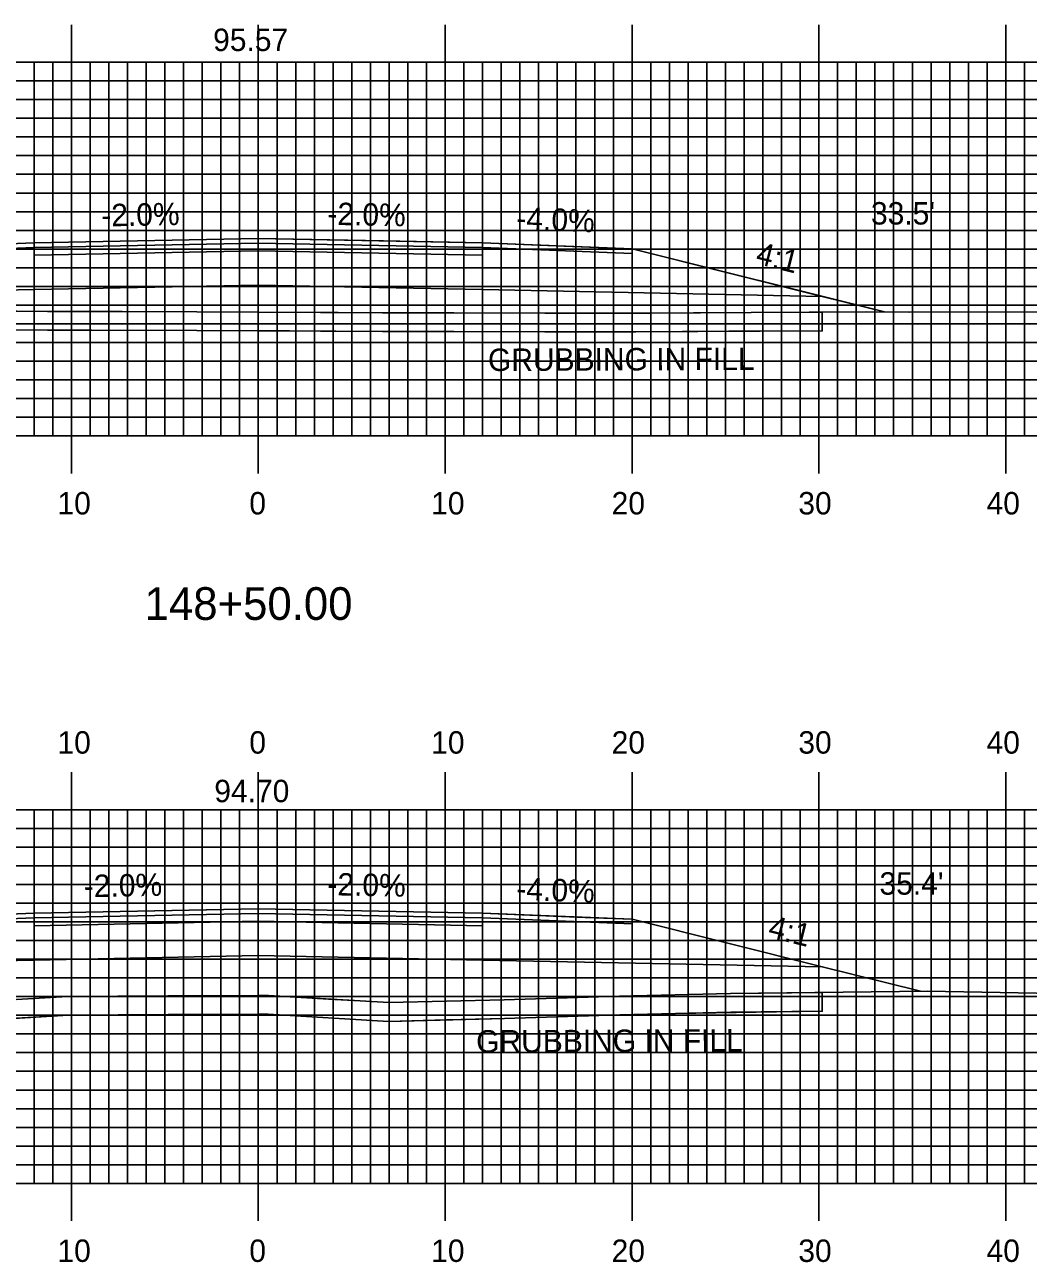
# Model space of a CAD drawing. Extents: x 1777925 to 1778268, y 442591 to 442811.
# Drawn here: x 1778078.3 to 1778132, y 442689.4 to 442755.7 of the extents above; entities that cross this region are included whole.
import ezdxf

# ---------------------------------------------------------------- set-up
doc = ezdxf.new("R2010")
doc.units = 0
for name, color, linetype in [('ANNOTATION', 7, 'Continuous'), ('D_Roadway_Centerline', 7, 'Continuous'), ('D_Roadway_Centerline_Text', 7, 'Continuous'), ('D_Roadway_Edge_Shoulder', 7, 'Continuous'), ('D_Roadway_Edge_TW', 7, 'Continuous'), ('D_Roadway_Pavement', 7, 'Continuous'), ('D_Roadway_SlopeLines', 7, 'Continuous'), ('D_Roadway_SubGrade', 7, 'Continuous'), ('D_Text_Standard', 7, 'Continuous'), ('GRUBBING IN FILL', 7, 'Continuous'), ('H_V ANNOTATION', 7, 'Continuous'), ('MAJOR', 7, 'Continuous'), ('MINOR', 7, 'Continuous'), ('S_Roadway_Centerline', 7, 'Continuous')]:
    doc.layers.add(name, color=color, linetype=linetype)

msp = doc.modelspace()

# ---------------------------------------------------------------- linework, layer by layer
at = {"layer": 'D_Roadway_Centerline'}
for points in [[(1778058.344, 442740.566), (1778060.616, 442741.134), (1778070.79, 442743.677), (1778078.79, 442743.997), (1778090.789, 442744.237), (1778090.79, 442744.237), (1778097.486, 442744.103), (1778102.79, 442743.997), (1778107.608, 442743.804), (1778110.79, 442743.677), (1778120.964, 442741.134), (1778124.306, 442740.299)], [(1778125.608, 442740.297), (1778125.616, 442740.297)], [(1778052.326, 442703.186), (1778053.506, 442703.481), (1778058.79, 442704.802), (1778059.096, 442704.879), (1778060.616, 442705.259), (1778065.395, 442706.454), (1778070.79, 442707.802), (1778078.79, 442708.122), (1778088.92, 442708.325), (1778090.79, 442708.362), (1778102.79, 442708.122), (1778108.283, 442707.902), (1778110.79, 442707.802), (1778120.964, 442705.259), (1778126.218, 442703.946)]]:
    msp.add_lwpolyline(points, dxfattribs=at)
at = {"layer": 'D_Roadway_Edge_Shoulder'}
for points in [[(1778078.79, 442743.997), (1778070.79, 442743.677), (1778070.79, 442743.427), (1778078.79, 442743.747)], [(1778102.79, 442743.997), (1778110.79, 442743.677), (1778110.79, 442743.427), (1778102.79, 442743.747)], [(1778078.79, 442708.122), (1778070.79, 442707.802), (1778070.79, 442707.552), (1778078.79, 442707.872)], [(1778102.79, 442708.122), (1778110.79, 442707.802), (1778110.79, 442707.552), (1778102.79, 442707.872)]]:
    msp.add_lwpolyline(points, close=True, dxfattribs=at)
at = {"layer": 'D_Roadway_Edge_TW'}
for points in [[(1778078.79, 442743.747), (1778078.79, 442743.997), (1778090.79, 442744.237), (1778102.79, 442743.997), (1778102.79, 442743.747), (1778090.79, 442743.987)], [(1778078.79, 442707.872), (1778078.79, 442708.122), (1778090.79, 442708.362), (1778102.79, 442708.122), (1778102.79, 442707.872), (1778090.79, 442708.112)]]:
    msp.add_lwpolyline(points, close=True, dxfattribs=at)
at = {"layer": 'D_Roadway_Pavement'}
for points in [[(1778078.79, 442743.331), (1778078.79, 442743.747), (1778090.79, 442743.987), (1778102.79, 442743.747), (1778102.79, 442743.331), (1778090.79, 442743.571)], [(1778078.79, 442707.456), (1778078.79, 442707.872), (1778090.79, 442708.112), (1778102.79, 442707.872), (1778102.79, 442707.456), (1778090.79, 442707.696)]]:
    msp.add_lwpolyline(points, close=True, dxfattribs=at)
at = {"layer": 'D_Roadway_SlopeLines'}
for points in [[(1778110.79, 442743.677), (1778124.305, 442740.299)], [(1778110.79, 442707.802), (1778120.964, 442705.259), (1778126.218, 442703.946)]]:
    msp.add_lwpolyline(points, dxfattribs=at)
at = {"layer": 'D_Roadway_SubGrade'}
for points in [[(1778078.79, 442741.497), (1778060.616, 442741.134), (1778070.79, 442743.677), (1778070.79, 442743.427), (1778078.79, 442743.747), (1778090.79, 442743.987), (1778102.79, 442743.747), (1778110.79, 442743.427), (1778110.79, 442743.677), (1778120.964, 442741.134), (1778102.79, 442741.497), (1778090.79, 442741.737)], [(1778078.79, 442705.622), (1778060.616, 442705.259), (1778070.79, 442707.802), (1778070.79, 442707.552), (1778078.79, 442707.872), (1778090.79, 442708.112), (1778102.79, 442707.872), (1778110.79, 442707.552), (1778110.79, 442707.802), (1778120.964, 442705.259), (1778102.79, 442705.622), (1778090.79, 442705.862)]]:
    msp.add_lwpolyline(points, close=True, dxfattribs=at)
at = {"layer": 'GRUBBING IN FILL'}
for p, q in [((1778120.964, 442740.288), (1778120.964, 442739.288)), ((1778120.964, 442740.288), (1778120.964, 442739.288)), ((1778120.964, 442703.882), (1778120.964, 442702.882)), ((1778120.964, 442703.882), (1778120.964, 442702.882))]:
    msp.add_line(p, q, dxfattribs=at)
for points in [[(1778060.616, 442740.537), (1778064.057, 442740.494), (1778072.934, 442740.381), (1778076.219, 442740.352), (1778079.504, 442740.324), (1778083.5, 442740.316), (1778087.496, 442740.308), (1778090.79, 442740.292), (1778090.79, 442739.292), (1778087.492, 442739.308), (1778076.211, 442739.352), (1778072.923, 442739.381), (1778066.77, 442739.459), (1778060.616, 442739.537)], [(1778060.616, 442740.537), (1778064.057, 442740.494), (1778072.934, 442740.381), (1778076.219, 442740.352), (1778079.504, 442740.324), (1778083.5, 442740.316), (1778087.496, 442740.308), (1778090.79, 442740.292), (1778090.79, 442739.292), (1778087.492, 442739.308), (1778076.211, 442739.352), (1778072.923, 442739.381), (1778066.77, 442739.459), (1778060.616, 442739.537)], [(1778090.79, 442740.292), (1778099.344, 442740.254), (1778106.117, 442740.243), (1778111.758, 442740.234), (1778117.172, 442740.27), (1778120.964, 442740.288), (1778120.964, 442739.288), (1778115.977, 442739.264), (1778110.991, 442739.24), (1778106.117, 442739.243), (1778101.244, 442739.246), (1778097.437, 442739.262), (1778092.465, 442739.285), (1778090.79, 442739.292)], [(1778090.79, 442740.292), (1778099.344, 442740.254), (1778106.117, 442740.243), (1778111.758, 442740.234), (1778117.172, 442740.27), (1778120.964, 442740.288), (1778120.964, 442739.288), (1778115.977, 442739.264), (1778110.991, 442739.24), (1778106.117, 442739.243), (1778101.244, 442739.246), (1778097.437, 442739.262), (1778092.465, 442739.285), (1778090.79, 442739.292)], [(1778060.616, 442702.49), (1778060.616, 442703.49), (1778064.022, 442703.478), (1778069.212, 442703.46), (1778075.082, 442703.34), (1778080.576, 442703.67), (1778085.956, 442703.697), (1778090.79, 442703.721), (1778090.79, 442702.721), (1778085.958, 442702.697), (1778080.608, 442702.67), (1778077.855, 442702.505), (1778075.101, 442702.339), (1778072.151, 442702.4), (1778069.2, 442702.46)], [(1778060.616, 442702.49), (1778060.616, 442703.49), (1778064.022, 442703.478), (1778069.212, 442703.46), (1778075.082, 442703.34), (1778080.576, 442703.67), (1778085.956, 442703.697), (1778090.79, 442703.721), (1778090.79, 442702.721), (1778085.958, 442702.697), (1778080.608, 442702.67), (1778077.855, 442702.505), (1778075.101, 442702.339), (1778072.151, 442702.4), (1778069.2, 442702.46)], [(1778090.79, 442703.721), (1778091.336, 442703.724), (1778094.551, 442703.532), (1778096.234, 442703.432), (1778097.767, 442703.341), (1778100.853, 442703.417), (1778103.938, 442703.493), (1778110.111, 442703.685), (1778116.06, 442703.822), (1778120.964, 442703.882), (1778120.964, 442702.882), (1778118.521, 442702.852), (1778113.108, 442702.754), (1778110.139, 442702.686), (1778103.966, 442702.493), (1778100.858, 442702.417), (1778097.749, 442702.34), (1778091.308, 442702.724), (1778090.79, 442702.721)], [(1778090.79, 442703.721), (1778091.336, 442703.724), (1778094.551, 442703.532), (1778096.234, 442703.432), (1778097.767, 442703.341), (1778100.853, 442703.417), (1778103.938, 442703.493), (1778110.111, 442703.685), (1778116.06, 442703.822), (1778120.964, 442703.882), (1778120.964, 442702.882), (1778118.521, 442702.852), (1778113.108, 442702.754), (1778110.139, 442702.686), (1778103.966, 442702.493), (1778100.858, 442702.417), (1778097.749, 442702.34), (1778091.308, 442702.724), (1778090.79, 442702.721)]]:
    msp.add_lwpolyline(points, close=True, dxfattribs=at)
for points in [[(1778060.616, 442739.537), (1778072.923, 442739.381), (1778079.499, 442739.324), (1778087.492, 442739.308), (1778097.437, 442739.262), (1778101.244, 442739.246), (1778110.991, 442739.24), (1778120.964, 442739.288)], [(1778060.616, 442739.537), (1778072.923, 442739.381), (1778079.499, 442739.324), (1778087.492, 442739.308), (1778097.437, 442739.262), (1778101.244, 442739.246), (1778110.991, 442739.24), (1778120.964, 442739.288)], [(1778060.616, 442702.49), (1778069.2, 442702.46), (1778075.101, 442702.339), (1778080.608, 442702.67), (1778091.308, 442702.724), (1778097.749, 442702.34), (1778103.966, 442702.493), (1778110.139, 442702.686), (1778116.078, 442702.822), (1778120.964, 442702.882)], [(1778060.616, 442702.49), (1778069.2, 442702.46), (1778075.101, 442702.339), (1778080.608, 442702.67), (1778091.308, 442702.724), (1778097.749, 442702.34), (1778103.966, 442702.493), (1778110.139, 442702.686), (1778116.078, 442702.822), (1778120.964, 442702.882)]]:
    msp.add_lwpolyline(points, dxfattribs=at)
at = {"layer": 'MAJOR'}
for p, q in [((1778080.79, 442755.669), (1778080.79, 442753.665)), ((1778090.79, 442755.669), (1778090.79, 442753.665)), ((1778100.79, 442755.669), (1778100.79, 442753.665)), ((1778110.79, 442755.669), (1778110.79, 442753.665)), ((1778120.79, 442755.669), (1778120.79, 442753.665)), ((1778130.79, 442755.669), (1778130.79, 442753.665)), ((1777950.79, 442753.665), (1778230.79, 442753.665)), ((1777950.79, 442753.665), (1778230.79, 442753.665)), ((1778080.79, 442733.665), (1778080.79, 442753.665)), ((1778090.79, 442733.665), (1778090.79, 442753.665)), ((1778100.79, 442733.665), (1778100.79, 442753.665)), ((1778110.79, 442733.665), (1778110.79, 442753.665)), ((1778120.79, 442733.665), (1778120.79, 442753.665)), ((1778130.79, 442733.665), (1778130.79, 442753.665)), ((1777950.79, 442748.665), (1778230.79, 442748.665)), ((1777950.79, 442743.665), (1778230.79, 442743.665)), ((1777950.79, 442738.665), (1778230.79, 442738.665)), ((1777950.79, 442733.665), (1778230.79, 442733.665)), ((1777950.79, 442733.665), (1778230.79, 442733.665)), ((1778080.79, 442731.661), (1778080.79, 442733.665)), ((1778090.79, 442731.661), (1778090.79, 442733.665)), ((1778100.79, 442731.661), (1778100.79, 442733.665)), ((1778110.79, 442731.661), (1778110.79, 442733.665)), ((1778120.79, 442731.661), (1778120.79, 442733.665)), ((1778130.79, 442731.661), (1778130.79, 442733.665)), ((1778080.79, 442715.669), (1778080.79, 442713.665)), ((1778090.79, 442715.669), (1778090.79, 442713.665)), ((1778100.79, 442715.669), (1778100.79, 442713.665)), ((1778110.79, 442715.669), (1778110.79, 442713.665)), ((1778120.79, 442715.669), (1778120.79, 442713.665)), ((1778130.79, 442715.669), (1778130.79, 442713.665)), ((1777950.79, 442713.665), (1778230.79, 442713.665)), ((1777950.79, 442713.665), (1778230.79, 442713.665)), ((1778080.79, 442693.665), (1778080.79, 442713.665)), ((1778090.79, 442693.665), (1778090.79, 442713.665)), ((1778100.79, 442693.665), (1778100.79, 442713.665)), ((1778110.79, 442693.665), (1778110.79, 442713.665)), ((1778120.79, 442693.665), (1778120.79, 442713.665)), ((1778130.79, 442693.665), (1778130.79, 442713.665)), ((1777950.79, 442708.665), (1778230.79, 442708.665)), ((1777950.79, 442703.665), (1778230.79, 442703.665)), ((1777950.79, 442698.665), (1778230.79, 442698.665)), ((1777950.79, 442693.665), (1778230.79, 442693.665)), ((1777950.79, 442693.665), (1778230.79, 442693.665)), ((1778080.79, 442691.661), (1778080.79, 442693.665)), ((1778090.79, 442691.661), (1778090.79, 442693.665)), ((1778100.79, 442691.661), (1778100.79, 442693.665)), ((1778110.79, 442691.661), (1778110.79, 442693.665)), ((1778120.79, 442691.661), (1778120.79, 442693.665)), ((1778130.79, 442691.661), (1778130.79, 442693.665))]:
    msp.add_line(p, q, dxfattribs=at)
at = {"layer": 'MINOR'}
for p, q in [((1778078.79, 442733.665), (1778078.79, 442753.665)), ((1778079.79, 442733.665), (1778079.79, 442753.665)), ((1778081.79, 442733.665), (1778081.79, 442753.665)), ((1778082.79, 442733.665), (1778082.79, 442753.665)), ((1778083.79, 442733.665), (1778083.79, 442753.665)), ((1778084.79, 442733.665), (1778084.79, 442753.665)), ((1778085.79, 442733.665), (1778085.79, 442753.665)), ((1778086.79, 442733.665), (1778086.79, 442753.665)), ((1778087.79, 442733.665), (1778087.79, 442753.665)), ((1778088.79, 442733.665), (1778088.79, 442753.665)), ((1778089.79, 442733.665), (1778089.79, 442753.665)), ((1778091.79, 442733.665), (1778091.79, 442753.665)), ((1778092.79, 442733.665), (1778092.79, 442753.665)), ((1778093.79, 442733.665), (1778093.79, 442753.665)), ((1778094.79, 442733.665), (1778094.79, 442753.665)), ((1778095.79, 442733.665), (1778095.79, 442753.665)), ((1778096.79, 442733.665), (1778096.79, 442753.665)), ((1778097.79, 442733.665), (1778097.79, 442753.665)), ((1778098.79, 442733.665), (1778098.79, 442753.665)), ((1778099.79, 442733.665), (1778099.79, 442753.665)), ((1778101.79, 442733.665), (1778101.79, 442753.665)), ((1778102.79, 442733.665), (1778102.79, 442753.665)), ((1778103.79, 442733.665), (1778103.79, 442753.665)), ((1778104.79, 442733.665), (1778104.79, 442753.665)), ((1778105.79, 442733.665), (1778105.79, 442753.665)), ((1778106.79, 442733.665), (1778106.79, 442753.665)), ((1778107.79, 442733.665), (1778107.79, 442753.665)), ((1778108.79, 442733.665), (1778108.79, 442753.665)), ((1778109.79, 442733.665), (1778109.79, 442753.665)), ((1778111.79, 442733.665), (1778111.79, 442753.665)), ((1778112.79, 442733.665), (1778112.79, 442753.665)), ((1778113.79, 442733.665), (1778113.79, 442753.665)), ((1778114.79, 442733.665), (1778114.79, 442753.665)), ((1778115.79, 442733.665), (1778115.79, 442753.665)), ((1778116.79, 442733.665), (1778116.79, 442753.665)), ((1778117.79, 442733.665), (1778117.79, 442753.665)), ((1778118.79, 442733.665), (1778118.79, 442753.665)), ((1778119.79, 442733.665), (1778119.79, 442753.665)), ((1778121.79, 442733.665), (1778121.79, 442753.665)), ((1778122.79, 442733.665), (1778122.79, 442753.665)), ((1778123.79, 442733.665), (1778123.79, 442753.665)), ((1778124.79, 442733.665), (1778124.79, 442753.665)), ((1778125.79, 442733.665), (1778125.79, 442753.665)), ((1778126.79, 442733.665), (1778126.79, 442753.665)), ((1778127.79, 442733.665), (1778127.79, 442753.665)), ((1778128.79, 442733.665), (1778128.79, 442753.665)), ((1778129.79, 442733.665), (1778129.79, 442753.665)), ((1778131.79, 442733.665), (1778131.79, 442753.665)), ((1777950.79, 442752.665), (1778230.79, 442752.665)), ((1777950.79, 442751.665), (1778230.79, 442751.665)), ((1777950.79, 442750.665), (1778230.79, 442750.665)), ((1777950.79, 442749.665), (1778230.79, 442749.665)), ((1777950.79, 442747.665), (1778230.79, 442747.665)), ((1777950.79, 442746.665), (1778230.79, 442746.665)), ((1777950.79, 442745.665), (1778230.79, 442745.665)), ((1777950.79, 442744.665), (1778230.79, 442744.665)), ((1777950.79, 442742.665), (1778230.79, 442742.665)), ((1777950.79, 442741.665), (1778230.79, 442741.665)), ((1777950.79, 442740.665), (1778230.79, 442740.665)), ((1777950.79, 442739.665), (1778230.79, 442739.665)), ((1777950.79, 442737.665), (1778230.79, 442737.665)), ((1777950.79, 442736.665), (1778230.79, 442736.665)), ((1777950.79, 442735.665), (1778230.79, 442735.665)), ((1777950.79, 442734.665), (1778230.79, 442734.665)), ((1778078.79, 442693.665), (1778078.79, 442713.665)), ((1778079.79, 442693.665), (1778079.79, 442713.665)), ((1778081.79, 442693.665), (1778081.79, 442713.665)), ((1778082.79, 442693.665), (1778082.79, 442713.665)), ((1778083.79, 442693.665), (1778083.79, 442713.665)), ((1778084.79, 442693.665), (1778084.79, 442713.665)), ((1778085.79, 442693.665), (1778085.79, 442713.665)), ((1778086.79, 442693.665), (1778086.79, 442713.665)), ((1778087.79, 442693.665), (1778087.79, 442713.665)), ((1778088.79, 442693.665), (1778088.79, 442713.665)), ((1778089.79, 442693.665), (1778089.79, 442713.665)), ((1778091.79, 442693.665), (1778091.79, 442713.665)), ((1778092.79, 442693.665), (1778092.79, 442713.665)), ((1778093.79, 442693.665), (1778093.79, 442713.665)), ((1778094.79, 442693.665), (1778094.79, 442713.665)), ((1778095.79, 442693.665), (1778095.79, 442713.665)), ((1778096.79, 442693.665), (1778096.79, 442713.665)), ((1778097.79, 442693.665), (1778097.79, 442713.665)), ((1778098.79, 442693.665), (1778098.79, 442713.665)), ((1778099.79, 442693.665), (1778099.79, 442713.665)), ((1778101.79, 442693.665), (1778101.79, 442713.665)), ((1778102.79, 442693.665), (1778102.79, 442713.665)), ((1778103.79, 442693.665), (1778103.79, 442713.665)), ((1778104.79, 442693.665), (1778104.79, 442713.665)), ((1778105.79, 442693.665), (1778105.79, 442713.665)), ((1778106.79, 442693.665), (1778106.79, 442713.665)), ((1778107.79, 442693.665), (1778107.79, 442713.665)), ((1778108.79, 442693.665), (1778108.79, 442713.665)), ((1778109.79, 442693.665), (1778109.79, 442713.665)), ((1778111.79, 442693.665), (1778111.79, 442713.665)), ((1778112.79, 442693.665), (1778112.79, 442713.665)), ((1778113.79, 442693.665), (1778113.79, 442713.665)), ((1778114.79, 442693.665), (1778114.79, 442713.665)), ((1778115.79, 442693.665), (1778115.79, 442713.665)), ((1778116.79, 442693.665), (1778116.79, 442713.665)), ((1778117.79, 442693.665), (1778117.79, 442713.665)), ((1778118.79, 442693.665), (1778118.79, 442713.665)), ((1778119.79, 442693.665), (1778119.79, 442713.665)), ((1778121.79, 442693.665), (1778121.79, 442713.665)), ((1778122.79, 442693.665), (1778122.79, 442713.665)), ((1778123.79, 442693.665), (1778123.79, 442713.665)), ((1778124.79, 442693.665), (1778124.79, 442713.665)), ((1778125.79, 442693.665), (1778125.79, 442713.665)), ((1778126.79, 442693.665), (1778126.79, 442713.665)), ((1778127.79, 442693.665), (1778127.79, 442713.665)), ((1778128.79, 442693.665), (1778128.79, 442713.665)), ((1778129.79, 442693.665), (1778129.79, 442713.665)), ((1778131.79, 442693.665), (1778131.79, 442713.665)), ((1777950.79, 442712.665), (1778230.79, 442712.665)), ((1777950.79, 442711.665), (1778230.79, 442711.665)), ((1777950.79, 442710.665), (1778230.79, 442710.665)), ((1777950.79, 442709.665), (1778230.79, 442709.665)), ((1777950.79, 442707.665), (1778230.79, 442707.665)), ((1777950.79, 442706.665), (1778230.79, 442706.665)), ((1777950.79, 442705.665), (1778230.79, 442705.665)), ((1777950.79, 442704.665), (1778230.79, 442704.665)), ((1777950.79, 442702.665), (1778230.79, 442702.665)), ((1777950.79, 442701.665), (1778230.79, 442701.665)), ((1777950.79, 442700.665), (1778230.79, 442700.665)), ((1777950.79, 442699.665), (1778230.79, 442699.665)), ((1777950.79, 442697.665), (1778230.79, 442697.665)), ((1777950.79, 442696.665), (1778230.79, 442696.665)), ((1777950.79, 442695.665), (1778230.79, 442695.665)), ((1777950.79, 442694.665), (1778230.79, 442694.665))]:
    msp.add_line(p, q, dxfattribs=at)
at = {"layer": 'S_Roadway_Centerline'}
for points in [[(1777950.79, 442738.966), (1777955.192, 442738.991), (1777965.367, 442739.306), (1777978.504, 442739.313), (1777987.996, 442739.104), (1778001.991, 442739.387), (1778011.67, 442739.438), (1778026.292, 442739.932), (1778029.016, 442740.075), (1778032.096, 442740.028), (1778041.415, 442739.945), (1778050.527, 442740.466), (1778053.017, 442740.649), (1778055.18, 442740.606), (1778072.934, 442740.381), (1778079.504, 442740.324), (1778087.496, 442740.308), (1778097.442, 442740.262), (1778101.246, 442740.246), (1778110.988, 442740.24), (1778123.356, 442740.3), (1778145.529, 442740.267)], [(1778020.918, 442702.982), (1778036.728, 442703.212), (1778040.284, 442703.05), (1778045.106, 442703.135), (1778052.437, 442703.187), (1778058.831, 442703.496), (1778069.212, 442703.46), (1778075.082, 442703.34), (1778080.576, 442703.67), (1778091.336, 442703.724), (1778097.767, 442703.341), (1778103.938, 442703.493), (1778110.111, 442703.685), (1778116.06, 442703.822), (1778126.597, 442703.95), (1778139.237, 442703.725)]]:
    msp.add_lwpolyline(points, dxfattribs=at)

# ---------------------------------------------------------------- texts
at = {"layer": 'ANNOTATION'}
for s, rotation, p in [('-2.0%', 1.14571, (1778082.395, 442744.87)), ('-2.0%', 358.85424, (1778094.476, 442744.964)), ('-4.0%', 357.70927, (1778104.582, 442744.727)), ('4:1', 345.96529, (1778117.354, 442742.898)), ('-2.0%', 1.14576, (1778081.461, 442708.976)), ('-2.0%', 358.85424, (1778094.476, 442709.089)), ('-4.0%', 357.70926, (1778104.582, 442708.852)), ('4:1', 345.96756, (1778118.009, 442706.859))]:
    msp.add_text(s, height=1.2, rotation=rotation, dxfattribs=at).set_placement(p)
at = {"layer": 'D_Roadway_Centerline'}
for s, p in [('C', (1778090.785, 442744.237)), ('L', (1778090.79, 442744.23)), ('C', (1778090.785, 442708.362)), ('L', (1778090.79, 442708.355))]:
    msp.add_text(s, height=0.0146, dxfattribs=at).set_placement(p)
at = {"layer": 'D_Roadway_Centerline_Text'}
for s, p in [('95.57', (1778088.371, 442754.262)), ('94.70', (1778088.435, 442714.066))]:
    msp.add_text(s, height=1.2, dxfattribs=at).set_placement(p)
at = {"layer": 'D_Text_Standard'}
for s, p in [("33.5'", (1778123.576, 442744.978)), ("35.4'", (1778124.031, 442709.118))]:
    msp.add_text(s, height=1.2, dxfattribs=at).set_placement(p)
at = {"layer": 'GRUBBING IN FILL'}
for p in [(1778103.082, 442737.138), (1778102.45, 442700.664)]:
    msp.add_text('GRUBBING IN FILL', height=1.2, rotation=0.24521, dxfattribs=at).set_placement(p)
at = {"layer": 'H_V ANNOTATION'}
for s, height, p in [('10', 1.2, (1778080.041, 442729.465)), ('0', 1.2, (1778090.308, 442729.465)), ('10', 1.2, (1778100.041, 442729.465)), ('20', 1.2, (1778109.698, 442729.465)), ('30', 1.2, (1778119.687, 442729.465)), ('40', 1.2, (1778129.762, 442729.465)), ('148+50.00', 1.75, (1778084.704, 442723.821)), ('10', 1.2, (1778080.041, 442716.665)), ('0', 1.2, (1778090.308, 442716.665)), ('10', 1.2, (1778100.041, 442716.665)), ('20', 1.2, (1778109.698, 442716.665)), ('30', 1.2, (1778119.687, 442716.665)), ('40', 1.2, (1778129.762, 442716.665)), ('10', 1.2, (1778080.041, 442689.465)), ('0', 1.2, (1778090.308, 442689.465)), ('10', 1.2, (1778100.041, 442689.465)), ('20', 1.2, (1778109.698, 442689.465)), ('30', 1.2, (1778119.687, 442689.465)), ('40', 1.2, (1778129.762, 442689.465))]:
    msp.add_text(s, height=height, dxfattribs=at).set_placement(p)

doc.saveas('drawing.dxf')
